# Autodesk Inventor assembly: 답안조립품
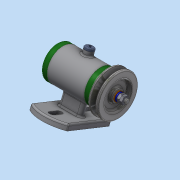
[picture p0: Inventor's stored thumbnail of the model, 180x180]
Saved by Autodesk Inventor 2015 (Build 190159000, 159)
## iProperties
Created: 2017-12
Part Number: 답안조립품
Document SubType Name: Assembly
Designer: SCD-A011
Author: SCD-A011
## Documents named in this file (14)
- D:\471208V1015\답안조립품.iam
- D:\471208V1015\V벨트풀리.ipt
- D:\471208V1015\고무캡.ipt
- D:\471208V1015\너트 M 8.ipt
- D:\471208V1015\뒤커버.ipt
- D:\471208V1015\베어링 15 x 32 x 9.ipt
- D:\471208V1015\본체.ipt
- D:\471208V1015\볼트 M4 x 12.ipt
- D:\471208V1015\스프링와셔 8.ipt
- D:\471208V1015\앞커버.ipt
- D:\471208V1015\오일 실 15 25 7.ipt
- D:\471208V1015\와셔 8x17.ipt
- D:\471208V1015\축.ipt
- D:\471208V1015\키 3 x 3 x 12.ipt
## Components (2 placed, 2 different names)
1. V벨트풀리:1
2. 고무캡:1
